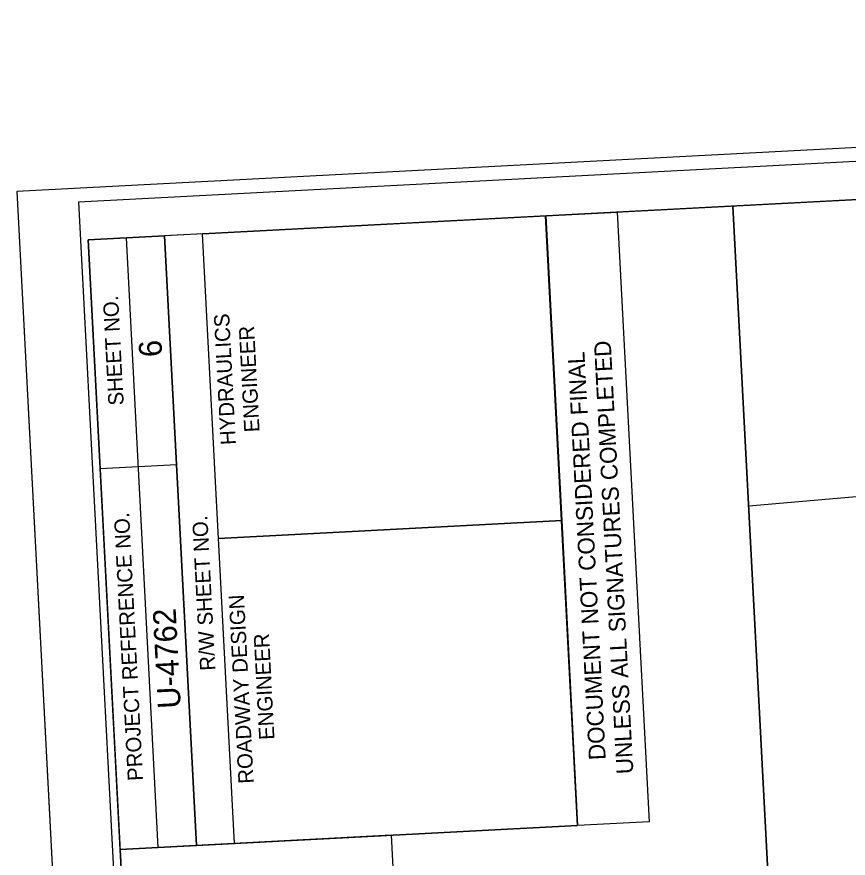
# Model space of a CAD drawing. Extents: x 2368224 to 2369406, y 803271 to 805009.
# Drawn here: x 2368224.2 to 2368496.5, y 804733.6 to 805009.3 of the extents above; entities that cross this region are included whole.
import ezdxf

# ---------------------------------------------------------------- set-up
doc = ezdxf.new("R2010")
doc.units = 0
for name, color, linetype in [('Old_Level_10', 7, 'Continuous'), ('Old_Level_15', 7, 'Continuous'), ('Old_Level_18', 7, 'Continuous'), ('Old_Level_3', 7, 'Continuous'), ('Old_Level_4', 7, 'Continuous'), ('Old_Level_6', 7, 'Continuous'), ('Plan Sheet CELL', 7, 'Continuous'), ('Plot Label CELL', 7, 'Continuous'), ('Plot Shape CELL', 7, 'Continuous')]:
    doc.layers.add(name, color=color, linetype=linetype)

msp = doc.modelspace()

# ---------------------------------------------------------------- linework, layer by layer
at = {"layer": 'Old_Level_10'}
for points in [[(2368326.05, 803438.23), (2369374.59, 803493.17), (2369296.14, 804991.12), (2368458.77, 804947.26), (2368471.29, 804708.34), (2368260.09, 804697.28)], [(2368471.29, 804708.34), (2368458.77, 804947.29), (2368247.57, 804936.25), (2368260.09, 804697.28)]]:
    msp.add_lwpolyline(points, close=True, dxfattribs=at)
at = {"layer": 'Old_Level_15'}
msp.add_line((2368224.23, 804952.01), (2368312.28, 803270.82), dxfattribs=at)
at = {"layer": 'Old_Level_18'}
for points in [[(2369225.56, 803658.81), (2369231.41, 803547.12), (2368322.69, 803502.45), (2368260.09, 804697.28), (2368471.29, 804708.34), (2368463.92, 804849.01), (2369156.05, 804909.28), (2369192.48, 804949.79), (2369298, 804955.52), (2369365.52, 803666.4)], [(2369225.56, 803658.81), (2369231.41, 803547.12), (2368322.69, 803502.45), (2368260.09, 804697.28), (2368471.29, 804708.34), (2368463.92, 804849.01), (2369156.05, 804909.28), (2369183.08, 804698.01), (2369311.04, 804706.52), (2369365.52, 803666.4)]]:
    msp.add_lwpolyline(points, close=True, dxfattribs=at)
at = {"layer": 'Old_Level_3'}
msp.add_lwpolyline([(2368258.03, 804736.44), (2368263.31, 804635.61), (2368352.17, 804640.27), (2368346.89, 804741.09)], close=True, dxfattribs=at)
at = {"layer": 'Old_Level_4'}
msp.add_lwpolyline([(2369385.12, 803340.02), (2369297.98, 805003.73), (2368244.44, 804948.57), (2368331.57, 803284.85)], close=True, dxfattribs=at)
at = {"layer": 'Old_Level_6'}
msp.add_lwpolyline([(2369405.78, 803328.09), (2369317.73, 805009.28), (2368224.23, 804952.01), (2368312.28, 803270.82)], close=True, dxfattribs=at)
at = {"layer": 'Plan Sheet CELL'}
for p, q in [((2368407.88, 804744.3), (2368397.42, 804944.06)), ((2368407.88, 804744.3), (2368397.42, 804944.06)), ((2368397.43, 804944.06), (2368420.9, 804945.29)), ((2368397.43, 804944.06), (2368420.9, 804945.29)), ((2368420.89, 804945.29), (2368431.35, 804745.53)), ((2368420.89, 804945.29), (2368431.35, 804745.53)), ((2368431.35, 804745.53), (2368407.88, 804744.3)), ((2368431.35, 804745.53), (2368407.88, 804744.3))]:
    msp.add_line(p, q, dxfattribs=at)
at = {"layer": 'Plot Shape CELL'}
for p, q in [((2368270.56, 804737.08), (2368260.11, 804936.86)), ((2368283.08, 804737.75), (2368272.59, 804937.51)), ((2368283.08, 804737.75), (2368272.59, 804937.51)), ((2368251.56, 804861.28), (2368276.53, 804862.64)), ((2368290.32, 804838.32), (2368402.62, 804844.21)), ((2368283.08, 804737.75), (2368295.55, 804738.4))]:
    msp.add_line(p, q, dxfattribs=at)
for points in [[(2368247.57, 804936.24), (2368326.02, 803438.25), (2369374.59, 803493.17), (2369296.14, 804991.13)], [(2369374.59, 803493.17), (2368326.05, 803438.23), (2368258.03, 804736.44), (2368407.88, 804744.3), (2368397.43, 804944.06), (2369296.14, 804991.13)], [(2368290.32, 804838.32), (2368285.08, 804938.17), (2368397.43, 804944.06), (2368402.68, 804844.2)], [(2368258.03, 804736.44), (2368247.57, 804936.24), (2368272.59, 804937.51), (2368283.08, 804737.75)], [(2368295.55, 804738.4), (2368290.32, 804838.32), (2368402.68, 804844.2), (2368407.88, 804744.3)]]:
    msp.add_lwpolyline(points, close=True, dxfattribs=at)

# ---------------------------------------------------------------- texts
at = {"layer": 'Plan Sheet CELL'}
for s, p in [('UNLESS ALL SIGNATURES COMPLETED', (2368426.16, 804761.28)), ('UNLESS ALL SIGNATURES COMPLETED', (2368426.16, 804761.28)), ('DOCUMENT NOT CONSIDERED FINAL', (2368417.11, 804765.88)), ('DOCUMENT NOT CONSIDERED FINAL', (2368417.11, 804765.88))]:
    msp.add_text(s, height=5.5, rotation=92.9979, dxfattribs=at).set_placement(p)
at = {"layer": 'Plot Label CELL'}
for s, p in [('6', (2368271.86, 804897.98)), ('U-4762', (2368277.95, 804782.77))]:
    msp.add_text(s, height=7.5, rotation=92.9979, dxfattribs=at).set_placement(p)
at = {"layer": 'Plot Shape CELL'}
for s, height, p in [('SHEET NO.', 5, (2368259.25, 804882.06)), ('HYDRAULICS', 5, (2368295.99, 804869.12)), ('ENGINEER', 5, (2368303.74, 804873.29)), ('PROJECT REFERENCE NO.', 5.0001, (2368265.58, 804759.06)), ('R/W SHEET NO.', 5.0001, (2368289.27, 804795.15)), ('ROADWAY DESIGN', 5.0001, (2368301.83, 804758.13)), ('ENGINEER', 5, (2368308.62, 804772.49))]:
    msp.add_text(s, height=height, rotation=92.9979, dxfattribs=at).set_placement(p)

doc.saveas('drawing.dxf')
